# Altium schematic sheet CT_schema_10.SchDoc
size 274 x 160 mm
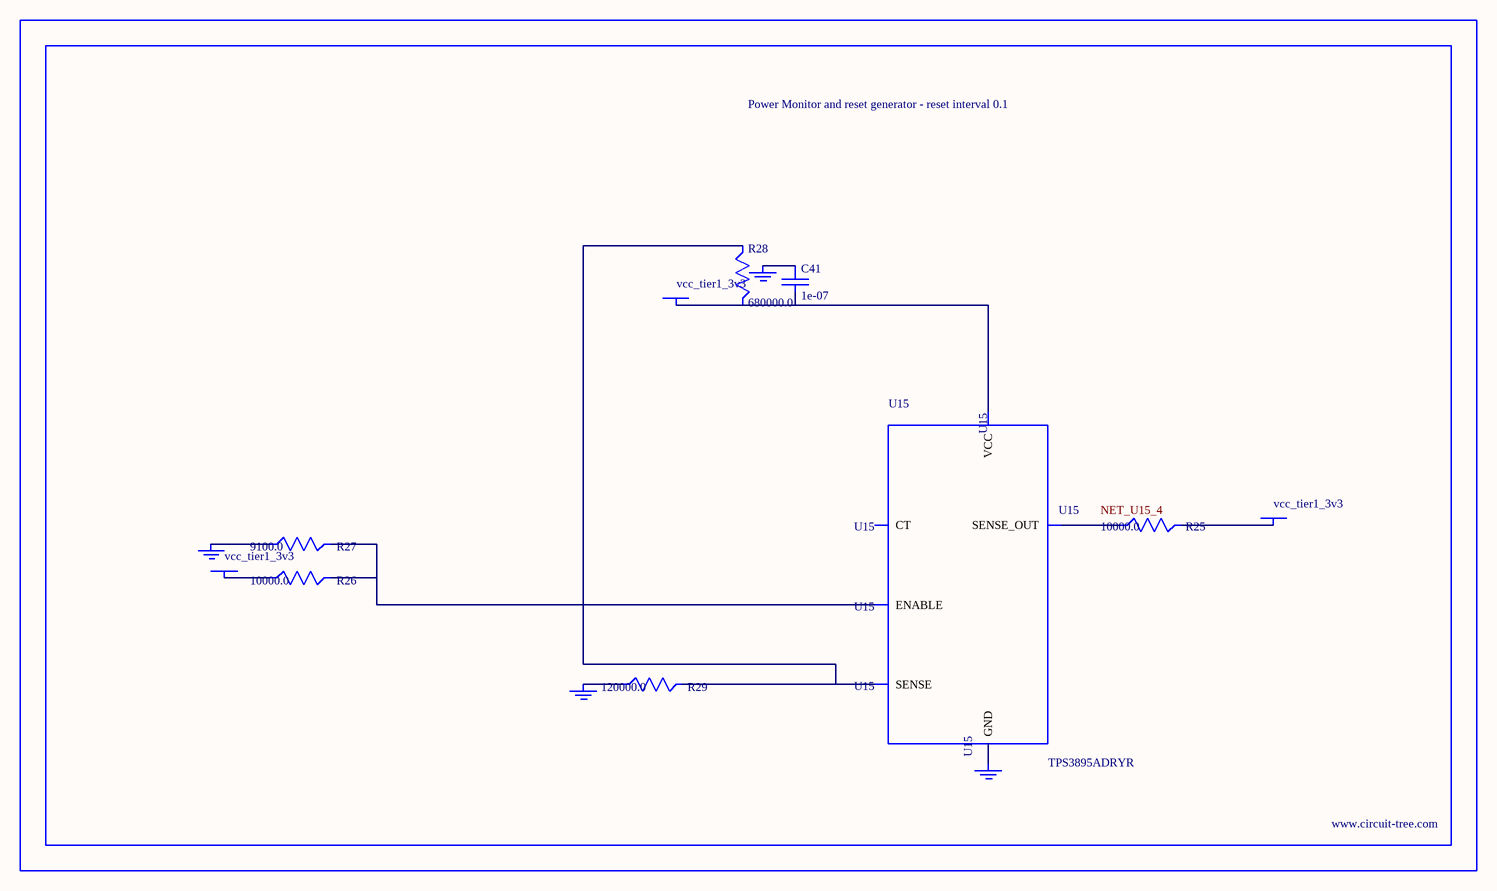
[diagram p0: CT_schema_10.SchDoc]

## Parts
BORDER9  (no value)
C41  1e-07  [C0402]
GND_INSTANCE_9_0  (no value)
GND_INSTANCE_9_1  (no value)
GND_INSTANCE_9_2  (no value)
GND_INSTANCE_9_3  (no value)
POWER_INSTANCE_9_0  vcc_tier1_3v3
POWER_INSTANCE_9_1  vcc_tier1_3v3
POWER_INSTANCE_9_2  vcc_tier1_3v3
R25  10000.0  [R0603]
R26  10000.0  [R0603]
R27  9100.0  [R0603]
R28  680000.0  [R0603]
R29  120000.0  [R0603]
U15  TPS3895ADRYR  [SON-6]

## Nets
NetC41_1: C41.1 GND_INSTANCE_9_2.0(GND)
NetC41_2: C41.2 POWER_INSTANCE_9_2.0(PWR) R28.2 U15.6(VCC)
NetGND_INSTANCE_9_0_0: GND_INSTANCE_9_0.0(GND) R27.1
NetGND_INSTANCE_9_1_0: GND_INSTANCE_9_1.0(GND) R29.1
NetGND_INSTANCE_9_3_0: GND_INSTANCE_9_3.0(GND) U15.2(GND)
NetPOWER_INSTANCE_9_0_0: POWER_INSTANCE_9_0.0(PWR) R26.1
NetPOWER_INSTANCE_9_1_0: POWER_INSTANCE_9_1.0(PWR) R25.2
NetR25_1: R25.1 U15.4(SENSE_OUT)
NetR26_2: R26.2 R27.2 U15.1(ENABLE)
NetR28_1: R28.1 R29.2 U15.3(SENSE)

Not connected (* = marked no-connect by the designer): U15 5(CT)

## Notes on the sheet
- Labels drawn without touching a wire or pin: NET_U15_4

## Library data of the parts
BORDER9 = BORDER_PAGE9
C41 = C0402C104K3RACTU
GND_INSTANCE_9_0-GND_INSTANCE_9_3 = GND
POWER_INSTANCE_9_0-POWER_INSTANCE_9_2 = PWR
R25 R26 = RC0603JR-0710KL
R27 = RC0603JR-079K1L
R28 = RC0603JR-07680KL
R29 = RC0603JR-07120KL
